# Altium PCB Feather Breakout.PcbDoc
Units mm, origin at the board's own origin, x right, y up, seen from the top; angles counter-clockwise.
Board outline 30.12 x 80 mm, 2 copper layers (Top Layer, Bottom Layer); 10 components, 5 nets, 43 pads, 0 vias.
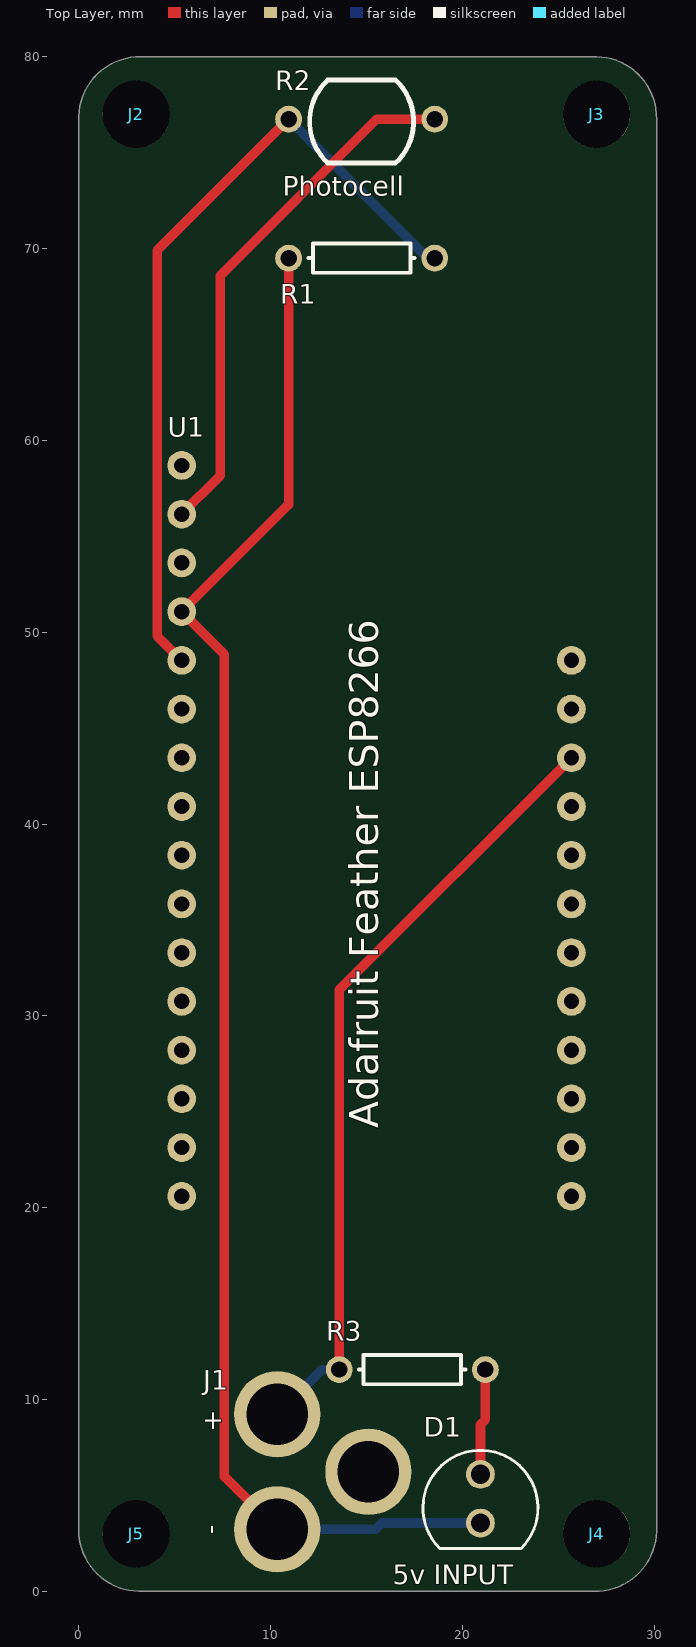
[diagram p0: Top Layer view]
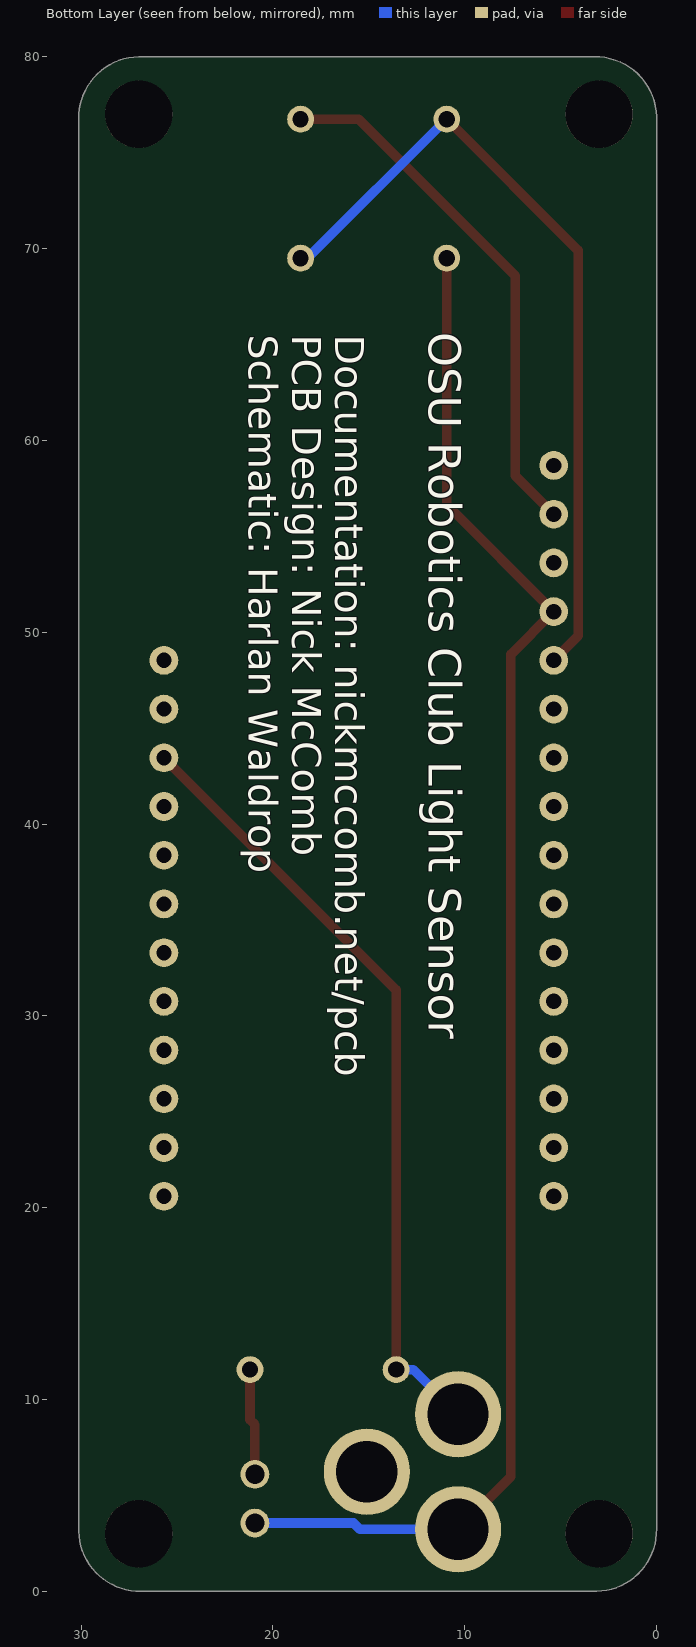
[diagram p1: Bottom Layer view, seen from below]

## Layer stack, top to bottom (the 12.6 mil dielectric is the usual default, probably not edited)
Top Solder: solder mask 0.0102, Solder Resist, Dk 3.5
Top Layer: signal copper 0.0356
Dielectric 1: dielectric 0.32, FR-4, Dk 4.8
Bottom Layer: signal copper 0.0356
Bottom Solder: solder mask 0.0102, Solder Resist, Dk 3.5

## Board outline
0,3.25 ccw(c3.187,3.187) 3.125,0 26.875,0 ccw(c26.938,3.187) 30.125,3.125 30.125,76.75 ccw(c26.938,76.813) 27,80 3.25,80 ccw(c3.187,76.813) 0,76.875

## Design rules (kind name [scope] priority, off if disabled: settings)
Clearance [All] p1: gap=0.254
HoleSize [All] p1: absolutevalues=TRUE maxlimit=4 minlimit=0.025 maxpercent=80.000 minpercent=20.000
PolygonConnect [All] p1: connectstyle=Relief reliefconductorwidth=0.254 reliefentries=4 polygonreliefangle="90 Angle" airgapwidth=0.254
RoutingVias [All] p1: holewidth=0.711 width=1.27 viastyle="Through Hole" minholewidth=0.711 minwidth=1.27 maxholewidth=0.711 maxwidth=1.27
SolderMaskExpansion [All] p1: expansion=0.102
Width [All] p1: maxlimit=0.5 minlimit=0.5 preferedwidth=0.5
29 further rules are at their usual default settings.

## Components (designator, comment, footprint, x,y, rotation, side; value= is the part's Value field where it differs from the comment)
D1 "Basic_LED" "Basic_LED - Through hole" 20.943,6.096 r270 top
J1 "BarrelJack_Female" BarrelJack 15.101,6.223 r270 top
J2 "MountingHoles" "Mounting Hole - Single"#1 47.498,3.556 r0 top
J3 "MountingHoles" "Mounting Hole - Single"#2 25.5,-6 r0 top
J4 "MountingHoles" "Mounting Hole - Single"#3 37.465,3.556 r0 top
J5 "MountingHoles" "Mounting Hole - Single"#4 2.667,2.54 r0 top
R1 "Res1" AXIAL-0.3 14.75,69.5 r0 top
R2 "Res Adj1" Photocell 14.75,76.75 r0 top
R3 "Res1" AXIAL-0.3 17.387,11.557 r0 top
U1 "Feather 8266" "ADAFRUIT FEATHER 8266" 6,62.375 r270 top

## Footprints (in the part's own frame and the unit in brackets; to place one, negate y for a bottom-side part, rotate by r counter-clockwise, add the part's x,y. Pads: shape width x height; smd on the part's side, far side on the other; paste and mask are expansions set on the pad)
"ADAFRUIT FEATHER 8266" [mm]
  round 1.5 hole 0.8: 1(3.683,-0.635) 2(6.223,-0.635) 3(8.763,-0.635) 4(11.303,-0.635) 5(13.843,-0.635) 6(16.383,-0.635) 7(18.923,-0.635) 8(21.463,-0.635) 9(24.003,-0.635) 10(26.543,-0.635) 11(29.083,-0.635) 12(31.623,-0.635) 13(34.163,-0.635) 14(36.703,-0.635) 15(39.243,-0.635) 16(41.783,-0.635) 17(41.783,19.685) 18(39.243,19.685) 19(36.703,19.685) 20(34.163,19.685) 21(31.623,19.685) 22(29.083,19.685) 23(26.543,19.685) 24(24.003,19.685) 25(21.463,19.685) 26(18.923,19.685) 27(16.383,19.685) 28(13.843,19.685)
AXIAL-0.3 [mm] "Axial Device, Thru-Hole; 2 Leads; 0.3 in Pin Spacing"
  round 1.4 hole 0.85: 1(-3.81,0) 2(3.81,0)
  silkscreen extent -2.77,-0.76 2.77,0.76
BarrelJack [mm] "Basic DC Barrel Jack"
  round 4.5 hole 3.2: 1(-3,-4.75) 2(3,-4.75) 3(0,0)
  body extent -3.7,-9.15 10.7,0.25, height 11.5
"Basic_LED - Through hole" [mm]
  round 1.5 hole 1: 1(0,0) 2(2.54,0)
  silkscreen extent -1.25,-3 3.87,3
"Mounting Hole - Single"#1 [mm]
  round 3.5 hole 3.5 unplated: A(-44.498,73.444)
"Mounting Hole - Single"#2 [mm]
  round 3.5 hole 3.5 unplated: A(1.5,83)
"Mounting Hole - Single"#3 [mm]
  round 3.5 hole 3.5 unplated: A(-10.465,-0.556)
"Mounting Hole - Single"#4 [mm]
  round 3.5 hole 3.5 unplated: A(0.333,0.46)
Photocell [mm] "Axial Device, Thru-Hole; 2 Leads; 0.3 in Pin Spacing"
  round 1.4 hole 0.85: 1(-3.81,0) 2(3.81,0)
  silkscreen extent -2.71,-2.29 2.71,2.03

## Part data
R1 R3: "Resistor"
R2: "Variable Resistor"

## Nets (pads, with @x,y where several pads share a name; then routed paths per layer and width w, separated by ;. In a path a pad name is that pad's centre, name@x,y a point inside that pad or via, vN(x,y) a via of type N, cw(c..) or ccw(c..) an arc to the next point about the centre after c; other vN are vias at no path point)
ESP_3V3: R2.2 U1.2 | length 27.8
  Top Layer w0.5: U1.2 7.366,58.153 7.366,68.58 15.536,76.75 R2.2
GND: D1.2 J1.2 R1.1 U1.4 | length 81.4
  Top Layer w0.5: J1.2 7.595,5.979 7.595,48.842 U1.4 10.94,56.647 R1.1
  Bottom Layer w0.5: J1.2 15.469,3.223 15.802,3.556 D1.2
NetD1_1: D1.1 R3.2 | length 5.6
  Top Layer w0.5: D1.1 20.943,8.687 21.197,8.941 R3.2
NetR1_2: R1.2 R2.1 U1.5 | length 42.2
  Top Layer w0.5: U1.5 4.089,49.808 4.089,69.899 R2.1
  Bottom Layer w0.5: R2.1 18.19,69.5 R1.2
USB_5V: J1.1 R3.1 U1.26 | length 41.1
  Top Layer w0.5: R3.1 13.577,31.344 U1.26
  Bottom Layer w0.5: J1.1 12.685,11.557 R3.1
pads on no net: J1.3 J2.A J3.A J4.A J5.A U1.1 U1.3 U1.6 U1.7 U1.8 U1.9 U1.10 U1.11 U1.12 U1.13 U1.14 U1.15 U1.16 U1.17 U1.18 U1.19 U1.20 U1.21 U1.22 U1.23 U1.24 U1.25 U1.27 U1.28

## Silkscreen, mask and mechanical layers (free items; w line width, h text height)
Top Overlay:
  text "Photocell" at 10.625,72.75 h1
  text "Adafruit Feather ESP8266" at 15.625,24.125 h1.5 r90
  text "5v INPUT" at 16.375,0.375 h1
Bottom Overlay:
  text "OSU Robotics Club Light Sensor" at 11.875,65.625 h1.7 r90
  text "Documentation: nickmccomb.net/pcb / PCB Design: Nick McComb   / Schematic: Harlan Waldrop" at 21.25,65.5 h1.5 r90
Mechanical 1:
  the board outline again, w0.254

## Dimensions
0,80.75 to 30,80.625 on Top Overlay
30.75,80 to 30.75,0 on Top Overlay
